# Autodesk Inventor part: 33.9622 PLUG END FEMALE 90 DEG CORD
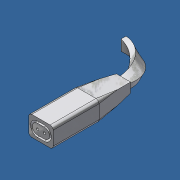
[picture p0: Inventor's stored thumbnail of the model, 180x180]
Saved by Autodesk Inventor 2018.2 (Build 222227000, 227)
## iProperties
Created: 2017-10
Part Number: 33.9622 PLUG END FEMALE 90 DEG CORD
Material: Generic
Document SubType Name: Modeling
Designer: Admin
Density: 1 g/cm^3
Appearance: Snow
Author: Admin
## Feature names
1. Extrusion8
2. Extrusion9
3. Extrusion10
4. Extrusion11
5. Fillet5
6. Sweep1
## Parameters: d38 = 16 mm, d39 = 13 mm, d41 = 0, d43 = 24 mm, d44 = -8 deg, d45 = 3.3 mm, d46 = 7 mm, d47 = 0.1 mm, d48 = 0, d50 = 0, d51 = 2 mm, d52 = 45 mm, d53 = 0, d54 = 90 deg
